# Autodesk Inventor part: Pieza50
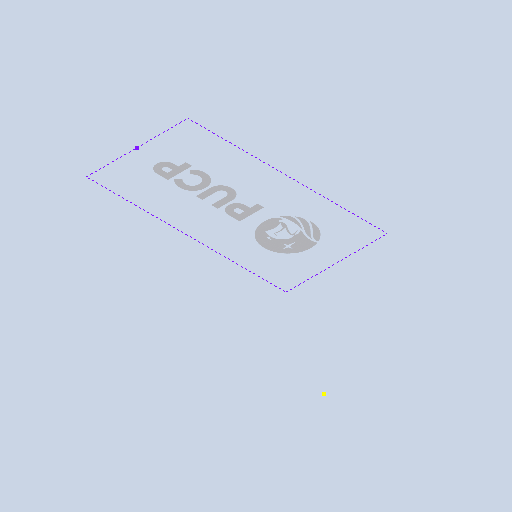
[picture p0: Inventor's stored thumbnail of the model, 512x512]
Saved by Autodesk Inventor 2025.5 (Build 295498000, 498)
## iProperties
Created: 2026-10
Part Number: Pieza50
Material: Genérico
Document SubType Name: Modeling
Designer: Luis M
Density: 1 g/cm^3
Appearance: Valor por defecto
Author: Luis M
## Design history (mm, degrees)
sketch "Boceto1"
  geometry: L1 (13.387, -8.621)-(38.387, -8.621); L2 (38.387, -8.621)-(38.387, -21.32); L3 (38.387, -21.32)-(13.387, -21.32); L4 (13.387, -21.32)-(13.387, -8.621); 2 further points; 1 other entity
  constraints: 1 midpoint, 3 other
  node "Imagen1"
